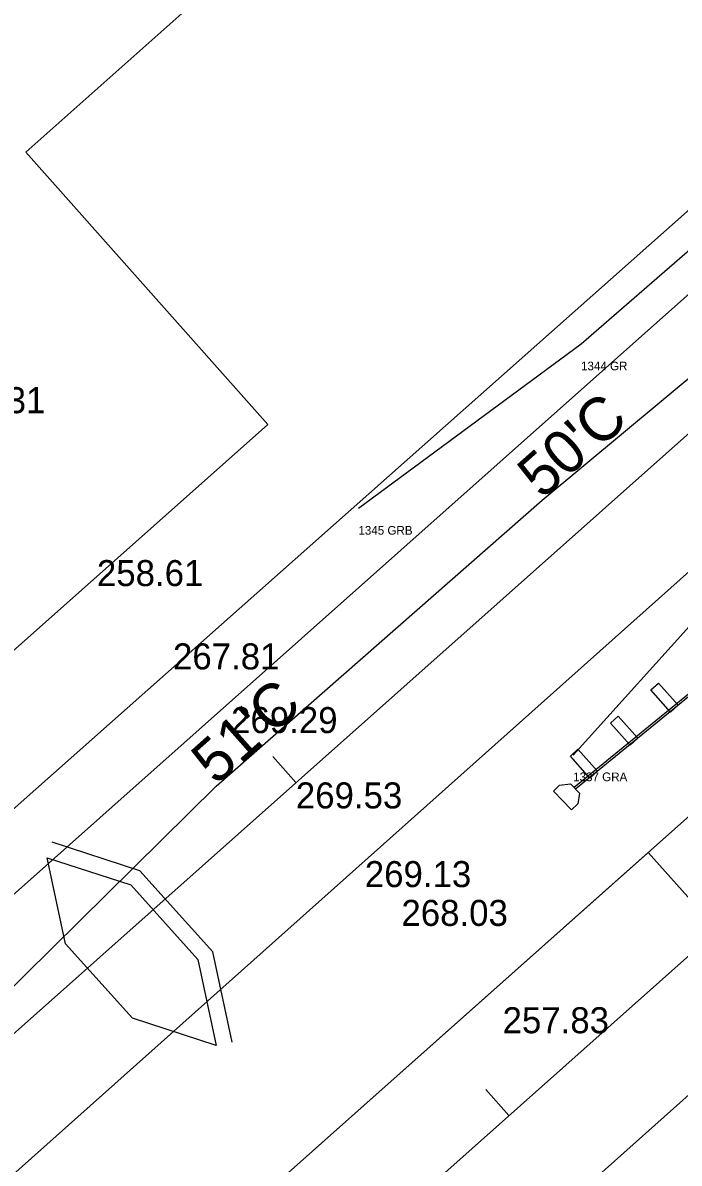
# Model space of a CAD drawing. Extents: x 49683 to 58852, y 49525 to 54803.
# Drawn here: x 53335.6 to 53411.3, y 51370.3 to 51501.8 of the extents above; entities that cross this region are included whole.
import ezdxf

# ---------------------------------------------------------------- set-up
doc = ezdxf.new("R2010")
doc.units = 0
for name, color, linetype in [('Level 1', 7, 'Continuous'), ('Level 11', 7, 'Continuous'), ('Level 13', 7, 'Continuous'), ('Level 18', 7, 'Continuous'), ('Level 19', 7, 'Continuous'), ('Level 20', 7, 'Continuous'), ('Level 27', 7, 'Continuous'), ('Level 3', 7, 'Continuous'), ('Level 32', 7, 'Continuous'), ('Level 34', 7, 'Continuous'), ('Level 48', 7, 'Continuous'), ('Level 57', 7, 'Continuous'), ('Level 7', 7, 'Continuous')]:
    doc.layers.add(name, color=color, linetype=linetype)

msp = doc.modelspace()

# ---------------------------------------------------------------- linework, layer by layer
at = {"layer": 'Level 1'}
for p, q in [((52544.81, 50683.3), (55534.58, 53340.86)), ((53367.09, 51414.21), (53364.43, 51417.2))]:
    msp.add_line(p, q, dxfattribs=at)
at = {"layer": 'Level 11'}
msp.add_line((53157.7, 51254.45), (53424.49, 51490.93), dxfattribs=at)
at = {"layer": 'Level 13'}
for p, q in [((53573.51, 51698.05), (53335.95, 51486.88)), ((53335.95, 51486.88), (53363.85, 51455.49)), ((52637.37, 50809.73), (53363.85, 51455.49)), ((53407.7, 51406.16), (52566.74, 50658.64)), ((53407.7, 51406.16), (53435.6, 51374.77))]:
    msp.add_line(p, q, dxfattribs=at)
at = {"layer": 'Level 18'}
for p, q in [((53395.48, 51446.76), (53443.15, 51486.46)), ((53357.89, 51413.79), (53395.48, 51446.76)), ((53322.27, 51378.61), (53357.89, 51413.79))]:
    msp.add_line(p, q, dxfattribs=at)
at = {"layer": 'Level 19'}
for p, q in [((52714.15, 50773.62), (54181.77, 52078.16)), ((53391.64, 51375.83), (53388.98, 51378.82))]:
    msp.add_line(p, q, dxfattribs=at)
at = {"layer": 'Level 20'}
for p, q in [((52706.17, 50782.58), (53452.43, 51445.92)), ((52722.12, 50764.65), (53468.37, 51427.98))]:
    msp.add_line(p, q, dxfattribs=at)
at = {"layer": 'Level 27'}
for p, q in [((53418.52, 51429.49), (53399.17, 51413.63)), ((53418.68, 51429.3), (53399.33, 51413.44)), ((53408, 51424.88), (53408.89, 51425.66)), ((53408.89, 51425.66), (53411.15, 51423.12)), ((53410.26, 51422.34), (53408, 51424.88)), ((53411.15, 51423.12), (53410.26, 51422.34)), ((53403.36, 51421.07), (53404.24, 51421.86)), ((53404.24, 51421.86), (53406.5, 51419.32)), ((53405.62, 51418.53), (53403.36, 51421.07)), ((53406.5, 51419.32), (53405.62, 51418.53)), ((53398.72, 51417.27), (53399.6, 51418.05)), ((53399.6, 51418.05), (53401.86, 51415.51)), ((53400.97, 51414.72), (53398.72, 51417.27)), ((53401.86, 51415.51), (53400.97, 51414.72))]:
    msp.add_line(p, q, dxfattribs=at)
msp.add_lwpolyline([(53397.49, 51413.91), (53398.73, 51414.07), (53399.77, 51413), (53399.58, 51411.76), (53398.86, 51411.06), (53396.77, 51413.22)], close=True, dxfattribs=at)
at = {"layer": 'Level 3'}
for p, q in [((53162.5, 51248.32), (53434.09, 51489.84)), ((53179.35, 51230.72), (53449.72, 51471.81))]:
    msp.add_line(p, q, dxfattribs=at)
at = {"layer": 'Level 34'}
for p, q in [((53349.11, 51404.04), (53338.99, 51407.33)), ((53340.52, 51395.63), (53338.41, 51405.55)), ((53338.41, 51405.55), (53348.06, 51402.42)), ((53357.53, 51394.7), (53349.11, 51404.04)), ((53348.06, 51402.42), (53355.8, 51393.82)), ((53348.26, 51387.04), (53340.52, 51395.63)), ((53359.74, 51384.29), (53357.53, 51394.7)), ((53355.8, 51393.82), (53357.9, 51383.9)), ((53357.9, 51383.9), (53348.26, 51387.04))]:
    msp.add_line(p, q, dxfattribs=at)
at = {"layer": 'Level 7'}
for p, q in [((53431.72, 51492.32), (53399.95, 51464.72)), ((53399.95, 51464.72), (53374.29, 51445.78)), ((53399.04, 51417.37), (53424.8, 51445.95))]:
    msp.add_line(p, q, dxfattribs=at)

# ---------------------------------------------------------------- texts
at = {"layer": 'Level 32'}
for s, p in [('256.31', (53325.94, 51456.78)), ('258.61', (53344.15, 51436.85)), ('267.81', (53352.92, 51427.25)), ('269.29', (53359.62, 51419.91)), ('269.53', (53367.08, 51411.23)), ('269.13', (53375.03, 51402.16)), ('268.03', (53379.25, 51397.69)), ('257.83', (53390.91, 51385.32))]:
    msp.add_text(s, height=3, dxfattribs=at).set_placement(p)
at = {"layer": 'Level 48'}
for s, p in [("50'C", (53395.48, 51446.76)), ("51'C", (53357.89, 51413.79))]:
    msp.add_text(s, height=5, rotation=41.6334, dxfattribs=at).set_placement(p)
at = {"layer": 'Level 57'}
for s, p in [('1344 GR', (53399.95, 51461.72)), ('1345 GRB', (53374.29, 51442.78)), ('1337 GRA', (53399.04, 51414.37))]:
    msp.add_text(s, height=1, dxfattribs=at).set_placement(p)

doc.saveas('drawing.dxf')
